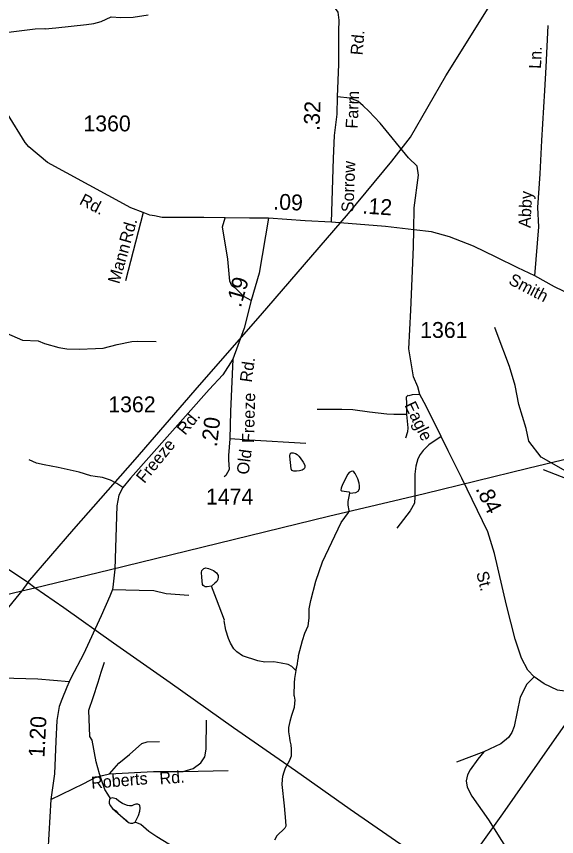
# Model space of a CAD drawing. Extents: x 1473865 to 1648260, y 639067 to 773536.
# Drawn here: x 1496300 to 1500545, y 650235 to 656681 of the extents above; entities that cross this region are included whole.
import ezdxf

# ---------------------------------------------------------------- set-up
doc = ezdxf.new("R2010")
doc.units = 0
for name, color, linetype in [('Exist Hydrographic Misc Water Feature', 7, 'Continuous'), ('Exist Road Non-System Type 51', 7, 'Continuous'), ('Exist Road Non-System Type 51 Label', 7, 'Continuous'), ('Exist Road Secondary Mileage Hundredths English Label', 7, 'Continuous'), ('Exist Road Secondary Type 51 Attributed', 7, 'Continuous'), ('Exist Road Secondary Type 51 Label', 7, 'Continuous'), ('Exist Road Secondary Type 51 Number Label', 7, 'Continuous'), ('Exist Utilities Electrical Transmission Line', 7, 'Continuous')]:
    doc.layers.add(name, color=color, linetype=linetype)

msp = doc.modelspace()

# ---------------------------------------------------------------- linework, layer by layer
at = {"layer": 'Exist Hydrographic Misc Water Feature'}
for points in [[(1495967.7, 656478.1), (1496024.8, 656501), (1496101.9, 656538.1), (1496139, 656552.4), (1496193.2, 656563.8), (1496238.1, 656557.7), (1496447.5, 656582.4), (1496521.9, 656586.3), (1496526.6, 656584.3), (1496610.7, 656590.7), (1496851.1, 656618.1), (1496907.2, 656625.1), (1496964.8, 656640.6), (1497044.1, 656678.4), (1497120, 656673), (1497216.1, 656675.2), (1497336.3, 656692.9)], [(1496116.2, 654237.4), (1496346.4, 654137.2), (1496470.2, 654130.9), (1496519.8, 654109.9), (1496633.3, 654079.8), (1496697.1, 654068.6), (1496793.1, 654066.8), (1496921, 654070.4), (1496981.1, 654073.3), (1497091.6, 654103.2), (1497206, 654127), (1497254, 654130.1), (1497398, 654125.4)], [(1501328.5, 652832.1), (1501250.4, 652861.8), (1501200.7, 652878.7), (1501141.2, 652903.8), (1500956.7, 652991.2), (1500849.4, 653025.2), (1500781.7, 653042.5), (1500664.5, 653084.6), (1500599.1, 653117.8), (1500424.9, 653217), (1500327.2, 653342.8), (1500305.1, 653443.2), (1500248.5, 653632.1), (1500219.2, 653780.6), (1500173.9, 653929.3), (1500078.5, 654187), (1500059.4, 654235.3)], [(1498528.7, 653211), (1498553.2, 653177.8), (1498567, 653154), (1498567.5, 653137.3), (1498562.3, 653124.8), (1498546.1, 653115.1), (1498525, 653110.5), (1498500.6, 653106.9), (1498478.8, 653107.3), (1498464.6, 653111.8), (1498458.3, 653125.4), (1498448.5, 653226.2), (1498451.4, 653244.6), (1498458.3, 653251.1), (1498475.9, 653252.4), (1498494.3, 653246.2), (1498505.9, 653237.5), (1498518.2, 653225.5), (1498528.7, 653211)], [(1498920.2, 652933.6), (1498968.3, 652940.6), (1498984.5, 652950.3), (1498996.8, 652968.1), (1498997.2, 652992.1), (1498993.6, 653012.1), (1498982.2, 653048.3), (1498962.9, 653088.6), (1498951.1, 653102.9), (1498943.2, 653107), (1498931.2, 653105.2), (1498915, 653097.5), (1498904.9, 653083.8), (1498863.4, 653002.6), (1498852.9, 652974.8), (1498850.6, 652958.8), (1498856.5, 652952.7), (1498912.4, 652945.7), (1498920.2, 652933.6)], [(1498496.5, 651541.6), (1498503.6, 651570.3), (1498508, 651594.2), (1498512.4, 651618), (1498516.8, 651641.9), (1498517.1, 651657.9), (1498547.3, 651777.3), (1498566.4, 651832.9), (1498593.4, 651892.4), (1498599.8, 651952.8), (1498599.8, 652024.2), (1498613, 652091.9), (1498651.7, 652243), (1498704.5, 652394), (1498852, 652703), (1498909.4, 652781.8), (1498913.7, 652797.8), (1498906.4, 652839.9), (1498906.9, 652869.8), (1498920.2, 652933.6)], [(1497832.6, 652202.8), (1497799, 652199.1), (1497783.1, 652199.4), (1497767.3, 652209.7), (1497763.4, 652217.8), (1497756.4, 652273.9), (1497755.2, 652311.8), (1497757.4, 652327.8), (1497771.7, 652341.5), (1497789.7, 652347.2), (1497809.7, 652342.8), (1497849.4, 652326.1), (1497873.1, 652307.6), (1497884.7, 652287.4), (1497886.5, 652277.4), (1497884, 652255.5), (1497873.8, 652239.7), (1497859.5, 652225.9), (1497832.6, 652202.8)], [(1498496.5, 651541.6), (1498463.6, 651571), (1498435.9, 651587.5), (1498380.1, 651598.6), (1498322.3, 651609.3), (1498252.3, 651607), (1498196.4, 651616), (1498077.2, 651656.2), (1498031.8, 651687), (1498008.2, 651711.5), (1497981, 651755.9), (1497967.7, 651792.2), (1497944.8, 651856.6), (1497932.5, 651929.8), (1497934.3, 651936.7), (1497873.3, 652101.8), (1497832.6, 652202.8)], [(1497039.2, 650534.9), (1497017, 650567.6), (1496994.9, 650604.6), (1496962.3, 650696.6), (1496952.7, 650728), (1496926.3, 650822.4), (1496895.5, 650992.8), (1496878, 651021.2), (1496869.8, 651229.2), (1496903.5, 651328.5), (1496941.6, 651447.7), (1496967, 651527.2), (1496992.6, 651606.6)], [(1498496.5, 651541.6), (1498485.9, 651476.7), (1498481.4, 651444.7), (1498479.5, 651346.9), (1498483.4, 651338.8), (1498486.8, 651306.7), (1498486.4, 651282.7), (1498481.8, 651250.9), (1498460.6, 651187.3), (1498447.8, 651139.6), (1498438.9, 651091.8), (1498438.4, 651059.8), (1498445.5, 651011.7), (1498449.1, 650987.7), (1498456.4, 650955.5), (1498459.9, 650923.5), (1498458.9, 650867.6), (1498444.1, 650827.8), (1498413.2, 650772.5), (1498400.6, 650740.7), (1498392.1, 650708.9), (1498387.6, 650685), (1498386.9, 650645), (1498403.8, 650476.8), (1498415.6, 650356.7), (1498417, 650316.7), (1498408.7, 650300.8), (1498347.6, 650240), (1498327, 650206.4)], [(1497233.2, 650347.6), (1497241.9, 650363.6), (1497259.6, 650401.8), (1497269.7, 650434.1), (1497271.9, 650457.5), (1497269, 650483.3), (1497254.6, 650491.4), (1497237.3, 650491.2), (1497223.2, 650484.8), (1497206.2, 650477.9), (1497188.3, 650477.2), (1497171.6, 650479.8), (1497152.7, 650486.9), (1497133.9, 650496.3), (1497105.2, 650514.8), (1497082.5, 650532), (1497053, 650539.4), (1497039.2, 650534.9)], [(1497039.2, 650534.9), (1497032.6, 650526.4), (1497028.4, 650511.4), (1497029.2, 650497.9), (1497037.3, 650480.4), (1497053.6, 650456.6), (1497080.5, 650436.9), (1497097.1, 650419.8), (1497137.7, 650383.2), (1497161.9, 650364.2), (1497181.1, 650346.4), (1497195.6, 650340.5), (1497214.5, 650340.1), (1497233.2, 650347.6)], [(1497039.2, 650534.9), (1497032.6, 650526.4), (1497028.4, 650511.4), (1497029.2, 650497.9), (1497037.3, 650480.4), (1497053.6, 650456.6), (1497137.7, 650383.2), (1497181.1, 650346.4), (1497195.6, 650340.5), (1497214.5, 650340.1), (1497233.2, 650347.6)], [(1498287.2, 649775.4), (1498271.2, 649773.8), (1498265.2, 649775.9), (1498092.6, 649849.1), (1498049, 649871.9), (1497972.2, 649946.8), (1497939.3, 650001.9), (1497853.1, 650097.4), (1497817.5, 650118.1), (1497756, 650147.2), (1497722.2, 650155.8), (1497666.2, 650156.9), (1497658.2, 650153.1), (1497594, 650144.3), (1497546, 650147.2), (1497402, 650232.8), (1497340.4, 650275), (1497277.4, 650330.1), (1497233.2, 650347.6)]]:
    msp.add_lwpolyline(points, dxfattribs=at)
at = {"layer": 'Exist Road Non-System Type 51'}
for p, q in [((1497296.5, 655139.5), (1497156.8, 654603.3)), ((1499974.5, 650902.7), (1499759.1, 650820))]:
    msp.add_line(p, q, dxfattribs=at)
for points in [[(1500416.3, 655442.9), (1500428.5, 655704.8), (1500453.9, 656099.5), (1500463.3, 656281.7), (1500480, 656608.6)], [(1499423.8, 655004.7), (1499427, 655177.3), (1499460.3, 655432.6), (1499449.7, 655505), (1499381.6, 655568.9), (1499158.9, 655841.9), (1499069.2, 655936.2), (1499025.9, 655978.4), (1498982.7, 656016), (1498918.9, 656038.8), (1498824.1, 656048.9)], [(1500373.8, 654641.2), (1500404.8, 655028), (1500397.2, 655180.4), (1500416.3, 655442.9)], [(1498143.7, 654448.3), (1498087.1, 654480.9), (1498023.9, 654542.7), (1497992.6, 654565.1), (1497977.2, 654601.2), (1497961.6, 654773.7), (1497920.5, 655027.4), (1497940.9, 655098)], [(1499470.8, 653711.1), (1499410.6, 653706.8), (1499383.9, 653699.2), (1499376.2, 653702.5), (1499363.8, 653689), (1499364.7, 653638), (1499365.8, 653552.2)], [(1499365.8, 653552.2), (1499264.7, 653552.2), (1499210.9, 653555.5), (1499073.9, 653570.1), (1498943.5, 653588.1), (1498857.1, 653591.4), (1498664.6, 653593)], [(1499365.8, 653552.2), (1499375.9, 653447.7), (1499373.5, 653416.1), (1499356.7, 653366)], [(1499638.5, 653380.1), (1499541.7, 653315.5), (1499496.6, 653270.3), (1499472.9, 653238), (1499455.7, 653203.6), (1499438.5, 653145.5), (1499432, 653083), (1499429.9, 652906.5), (1499427.7, 652854.8), (1499395.5, 652795.1), (1499290.1, 652659.5)], [(1498574, 653324.4), (1498132.4, 653351.3), (1497977, 653361.3)], [(1497137, 652979.1), (1497088.5, 653011.4), (1497038, 653037.7), (1496975.4, 653057.9), (1496918.9, 653066), (1496884.5, 653070), (1496793.6, 653100.3), (1496628, 653136.7), (1496518.9, 653156.9), (1496456.3, 653171.1), (1496399.7, 653195.4)], [(1501116, 652473.5), (1501131.6, 652656.3), (1501129.2, 652706.7), (1501118.2, 652745.5), (1501076.7, 652817.5), (1501021.1, 652879.9), (1500948.1, 652921.3), (1500442.9, 653118.2)], [(1497056, 652176.1), (1497263.7, 652171.2), (1497380.3, 652169.5), (1497476.7, 652145.7), (1497653.5, 652132.9)], [(1496715, 651451.3), (1496467.7, 651472.5), (1495990, 651485.2)], [(1500369.5, 651492.2), (1500312.5, 651433.2), (1500259, 651330.2), (1500211.6, 651100.8), (1500192.8, 651053.2), (1500166.2, 651013.7), (1500107.4, 650964.5), (1499974.5, 650902.7)], [(1497610.5, 650748), (1497688.7, 650769.2), (1497750, 650815.7), (1497779.6, 650862.3), (1497790.2, 650923.6), (1497794.4, 651149.9)], [(1497031.3, 650729), (1497105.3, 650811.5), (1497187.8, 650881.3), (1497285, 650965.9), (1497327.3, 650980.7), (1497424.5, 650982.8)], [(1499974.5, 650902.7), (1499925.4, 650843.5), (1499866.1, 650760.4), (1499845.5, 650719.4), (1499835, 650672.8), (1499842.2, 650622.8), (1499879, 650554.3), (1500010.1, 650366.1), (1500155.4, 650132.9), (1500252.3, 649984.4), (1500316.4, 649871.3)], [(1497031.3, 650729), (1497378, 650745.9), (1497610.5, 650748)], [(1497610.5, 650748), (1497963.5, 650754.4)], [(1496570.5, 650528), (1496830.5, 650652.8), (1496919.3, 650699.4), (1496976.4, 650714.2), (1497031.3, 650729)]]:
    msp.add_lwpolyline(points, dxfattribs=at)
at = {"layer": 'Exist Road Secondary Type 51 Attributed'}
for points in [[(1498281.9, 655096.5), (1498130.9, 655095), (1497940.9, 655098), (1497772.9, 655100.8), (1497589, 655099.9), (1497443.9, 655102), (1497386.1, 655113), (1497349.1, 655118.9), (1497296.5, 655139.5), (1497198.3, 655176.6), (1497019.6, 655272.9), (1496544.8, 655533.4), (1496397.8, 655656.4), (1496369.5, 655689.6), (1496229.3, 655915.6), (1496116.7, 656107), (1496006.7, 656228), (1495912.9, 656317.7), (1494702.9, 657180.2), (1494507.2, 657390.4), (1494363.8, 657601.6), (1493980.1, 658226.1)], [(1498774.9, 655063.7), (1498792.1, 655564.6), (1498798.8, 655746.1), (1498821.2, 655911.8), (1498824.1, 656048.9), (1498832.4, 656306.6), (1498833.8, 656566.4), (1498836.6, 656652), (1498828.1, 656715.2), (1498800.5, 656753.7)], [(1498281.9, 655096.5), (1498206.7, 654663.8), (1498143.7, 654448.3), (1498090.3, 654229.9), (1498001.1, 653987.1)], [(1498774.9, 655063.7), (1498568.5, 655075.6), (1498281.9, 655096.5)], [(1499423.8, 655004.7), (1499199.8, 655031.2), (1498774.9, 655063.7)], [(1501054.5, 651407.7), (1500882.4, 651381.7), (1500687.9, 651368.8), (1500551.9, 651385.5), (1500446.6, 651435.1), (1500369.5, 651492.2), (1500318.3, 651543.1), (1500268.1, 651637.7), (1500220.6, 651785.8), (1500152.6, 652054.9), (1500057.4, 652460.5), (1500003.9, 652631.7), (1499799.6, 653051.6), (1499692.3, 653266), (1499638.5, 653380.1), (1499520.3, 653618.5), (1499470.8, 653711.1), (1499453.6, 653769.2), (1499420, 653849), (1499382.7, 654069.8), (1499400, 654371.3), (1499419.8, 654870.9), (1499423.8, 655004.7)], [(1502993.3, 653578), (1502619.9, 653601.1), (1502464.7, 653621.5), (1502364.1, 653646.8), (1502325.8, 653662.7), (1502073.4, 653760.9), (1501996.1, 653801.3), (1501842.7, 653892.8), (1501330.8, 654157.6), (1501033.8, 654303.6), (1500943.9, 654346.2), (1500740.6, 654455), (1500528.1, 654556.3), (1500373.8, 654641.2), (1500241.2, 654705.4), (1500069.7, 654789.8), (1499891, 654876.6), (1499703.4, 654948.7), (1499561.4, 654987.5), (1499423.8, 655004.7)], [(1498001.1, 653987.1), (1497920.9, 653863.3), (1497815.6, 653748.6), (1497197.6, 653053.3), (1497137, 652979.1), (1497104.7, 652918.4), (1497088, 652836.1), (1497074.3, 652337.9), (1497058.3, 652196.7), (1497056, 652176.1), (1497033.1, 652125.7), (1496964.5, 651969.5), (1496827.5, 651669), (1496731.2, 651485.2), (1496715, 651451.3), (1496695.3, 651409.1), (1496657.7, 651313.8), (1496636.1, 651258.9), (1496617, 651146.8), (1496608.6, 650986), (1496598.6, 650727.6), (1496570.5, 650528), (1496537.6, 649980.9)], [(1498001.1, 653987.1), (1497982.8, 653576.9), (1497977, 653361.3), (1497965.6, 653229.1), (1497967.1, 653197)], [(1497967.1, 653197), (1497970.6, 653119.8), (1497945.7, 653073.6), (1497931.4, 653062.9)]]:
    msp.add_lwpolyline(points, dxfattribs=at)
at = {"layer": 'Exist Utilities Electrical Transmission Line'}
for p, q in [((1496390.7, 652231), (1496341.8, 652167.8)), ((1496444.1, 652190.1), (1496390.7, 652231)), ((1496341.8, 652167.8), (1496444.1, 652190.1))]:
    msp.add_line(p, q, dxfattribs=at)
for points in [[(1496390.7, 652231), (1496751.6, 652651), (1497232.6, 653199.1), (1497738.1, 653782.7), (1498217, 654330.7), (1498910.1, 655133.3), (1499250.7, 655543.7), (1499397.8, 655731.2), (1499673.7, 656214.7), (1500020.8, 656767)], [(1496390.7, 652231), (1495959.5, 652518), (1495247.2, 652998), (1494671.5, 653383.4), (1493906.1, 653916.3), (1493318.6, 654312), (1493057.3, 654482.3), (1492940.8, 654568.3), (1492819.5, 654734.3), (1492551.6, 655114.9), (1492217.1, 655572.4), (1491956.9, 655926.7)], [(1496444.1, 652190.1), (1497028.5, 652332.4), (1497885.9, 652542.2), (1498751.4, 652753.9), (1499508.2, 652931.3), (1500319.6, 653131.9), (1501191, 653339.4), (1501968, 653526.5), (1502578.4, 653670.4)], [(1499742.5, 649881.3), (1500123.3, 650413.1), (1500510.3, 650968.5), (1500891.2, 651510.3), (1501318.1, 652063.2), (1501665.5, 652509.5), (1502049.3, 652997.2), (1502362, 653402.1), (1502578.4, 653670.4)], [(1483279.5, 647207.2), (1484019.5, 647622), (1484772.4, 648043.4), (1485396.2, 648395.2), (1485969.4, 648721.6), (1486587.2, 649073.4), (1487279.6, 649460), (1487955.7, 649838.8), (1488571.2, 650172.5), (1488835.5, 650320.3), (1489363.7, 650447.5), (1490313.7, 650693.7), (1491223.4, 650922.7), (1492038.8, 651129.1), (1492741.7, 651307.5), (1493448.6, 651481.7), (1494000.7, 651614.7), (1494759.8, 651800.1), (1495420.2, 651953), (1496090.8, 652106), (1496341.8, 652167.8)], [(1496341.8, 652167.8), (1496058.1, 651824.5), (1495694.8, 651370.4), (1495251.9, 650827.8), (1494794.6, 650261.4), (1494259.8, 649592.2), (1493814.8, 649037.5), (1493337, 648443.4), (1492724.6, 647683.6), (1492300.8, 647149.4), (1491832.4, 646562.4), (1491364.9, 645978.1), (1490956.6, 645466.8), (1490599.2, 645018.8), (1490178.8, 644491.6), (1489291.2, 643370.4)], [(1499742.5, 649881.3), (1499388.5, 650125.1), (1498923.8, 650448.9), (1498492.7, 650752.1), (1498006.3, 651090.1), (1497508, 651444.5), (1497063.1, 651755.8), (1496671.6, 652032.2), (1496444.1, 652190.1)]]:
    msp.add_lwpolyline(points, dxfattribs=at)

# ---------------------------------------------------------------- texts
at = {"layer": 'Exist Road Non-System Type 51 Label'}
for s, rotation, p in [('Ln.', 87.87669, (1500422.4, 656268.3)), ('Abby', 87.19496, (1500339.9, 655017.5)), ('Rd.', 73.95066, (1497196.3, 654890.6)), ('Mann', 73.95066, (1497107.4, 654574.2)), ('Roberts', 4.82979, (1496890.7, 650610)), ('Rd.', 4.56, (1497427.6, 650644.9))]:
    msp.add_text(s, height=95, rotation=rotation, dxfattribs=at).set_placement(p)
at = {"layer": 'Exist Road Secondary Mileage Hundredths English Label'}
for s, rotation, p in [('.32', 87.81635, (1498681.2, 655781.2)), ('.09', 357.68088, (1498316.5, 655164.2)), ('.12', 356.28777, (1499016.4, 655132.3)), ('.19', 73.91327, (1498063, 654388.2)), ('.20', 83.03221, (1497874.9, 653294.1)), ('.84', 296.14689, (1499905.7, 652969.1)), ('1.20', 86.9926, (1496519.6, 650854.4))]:
    msp.add_text(s, height=125, rotation=rotation, dxfattribs=at).set_placement(p)
at = {"layer": 'Exist Road Secondary Type 51 Label'}
for s, rotation, p in [('Rd.', 85.00358, (1499019.1, 656373.6)), ('Farm', 87.81634, (1498981.8, 655798.2)), ('Sorrow', 87.81634, (1498948.4, 655140.8)), ('Rd.', 332.39986, (1496787.6, 655209.3)), ('Smith', 332.43689, (1500160.2, 654582.1)), ('Rd.', 82.09713, (1498148.5, 653801.2)), ('Freeze', 88.38307, (1498166, 653327.3)), ('Eagle', 296.07013, (1499347.3, 653626.5)), ('Rd.', 50.77147, (1497625.7, 653384.6)), ('Freeze', 50.77147, (1497304.9, 653005.7)), ('Old', 82.57542, (1498123.8, 653076.5)), ('St.', 284.18194, (1499912.6, 652308))]:
    msp.add_text(s, height=95, rotation=rotation, dxfattribs=at).set_placement(p)
at = {"layer": 'Exist Road Secondary Type 51 Number Label'}
for s, p in [('1360', (1496826.2, 655777.8)), ('1361', (1499473.2, 654154.4)), ('1362', (1497021.8, 653570)), ('1474', (1497789.9, 652845.1))]:
    msp.add_text(s, height=125, dxfattribs=at).set_placement(p)

doc.saveas('drawing.dxf')
